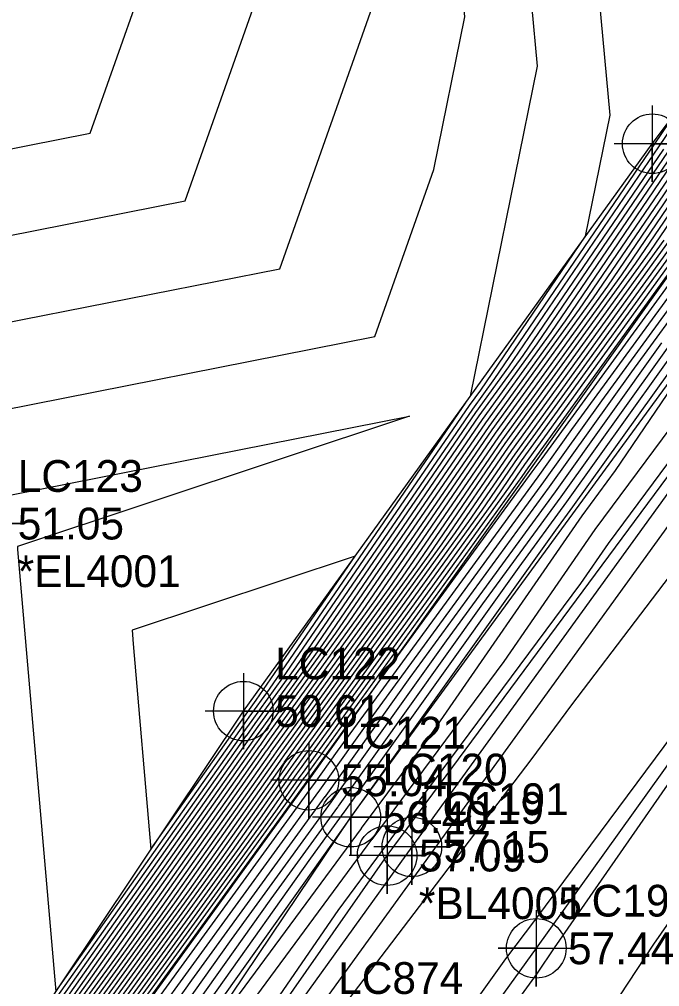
# Model space of a CAD drawing. Extents: x 2188792 to 2191981, y 386090 to 389710.
# Drawn here: x 2190040.5 to 2190090.9, y 387535.2 to 387611.4 of the extents above; entities that cross this region are included whole.
import ezdxf

# ---------------------------------------------------------------- set-up
doc = ezdxf.new("R2010")
doc.units = 0
for name, color, linetype in [('DTM Contours Major', 7, 'Continuous'), ('DTM Contours Minor', 7, 'Continuous'), ('Exist DTM Breakline', 7, 'Continuous'), ('Exist DTM Breakline Cogo Comment', 7, 'Continuous'), ('Exist DTM Breakline Cogo Elevation', 7, 'Continuous'), ('Exist DTM Breakline Cogo Number', 7, 'Continuous'), ('Exist DTM Breakline Cogo Point CELL', 7, 'Continuous'), ('Exist DTM Regular Point Underwater CELL', 7, 'Continuous'), ('Exist DTM Regular Point Underwater Cogo Comment', 7, 'Continuous'), ('Exist DTM Regular Point Underwater Cogo Elevation', 7, 'Continuous'), ('Exist DTM Regular Point Underwater Cogo Number', 7, 'Continuous'), ('Exist Roads EOP', 7, 'Continuous'), ('Exist Roads EOP Cogo Elevation', 7, 'Continuous'), ('Exist Roads EOP Cogo Number', 7, 'Continuous'), ('Exist Roads EOP Cogo Point CELL', 7, 'Continuous'), ('Exist Roads EOT', 7, 'Continuous'), ('Exist Roads EOT Cogo Elevation', 7, 'Continuous'), ('Exist Roads EOT Cogo Number', 7, 'Continuous'), ('Exist Roads EOT Cogo Point CELL', 7, 'Continuous')]:
    doc.layers.add(name, color=color, linetype=linetype)

msp = doc.modelspace()

# ---------------------------------------------------------------- linework, layer by layer
at = {"layer": 'DTM Contours Major'}
for points in [[(2190028.053, 387532.529), (2190026.213, 387539.316), (2190026.623, 387567.116), (2190036.437, 387572.281), (2190036.783, 387572.463), (2190037.624, 387573.49), (2190071.228, 387580.123), (2190040.365, 387569.873), (2190040.385, 387569.638), (2190043.386, 387534.826), (2190057.87, 387555.38), (2190057.878, 387555.392), (2190058.608, 387556.427), (2190060.211, 387558.646), (2190075.692, 387581.242), (2190075.723, 387581.285), (2190076.015, 387581.713), (2190081.298, 387607.701), (2190080.405, 387617.391)], [(2190041.85, 387529.933), (2190045.968, 387535.612), (2190059.191, 387554.377), (2190059.222, 387554.419), (2190059.771, 387555.199), (2190065.441, 387563.047), (2190076.972, 387579.879), (2190081.274, 387585.826), (2190091.608, 387600.993)], [(2190043.082, 387528.982), (2190051.636, 387540.776), (2190060.512, 387553.373), (2190060.566, 387553.447), (2190060.935, 387553.97), (2190070.671, 387567.449), (2190078.253, 387578.516), (2190086.825, 387590.366), (2190093.476, 387600.128)], [(2190045.546, 387527.079), (2190062.971, 387551.105), (2190063.155, 387551.367), (2190063.253, 387551.502), (2190063.261, 387551.513), (2190069.311, 387559.89), (2190080.892, 387575.741), (2190081.657, 387576.812), (2190097.263, 387598.2)], [(2190044.314, 387528.031), (2190057.303, 387545.941), (2190061.834, 387552.37), (2190061.909, 387552.475), (2190062.098, 387552.742), (2190075.901, 387571.851), (2190079.533, 387577.153), (2190092.376, 387594.907)], [(2190101.482, 387589.813), (2190086.86, 387570.121), (2190084.677, 387566.96), (2190069.08, 387545.942), (2190069.078, 387545.939), (2190065.584, 387541.202), (2190052.374, 387521.969)], [(2190048.167, 387524.986), (2190060.341, 387542.129), (2190065.593, 387549.358), (2190065.604, 387549.374), (2190065.633, 387549.414), (2190077.003, 387565.35), (2190083.158, 387573.776), (2190093.446, 387588.169)]]:
    msp.add_lwpolyline(points, dxfattribs=at)
at = {"layer": 'DTM Contours Minor'}
for points in [[(2190041.434, 387531.48), (2190058.134, 387555.179), (2190058.147, 387555.197), (2190058.841, 387556.182), (2190061.257, 387559.526), (2190075.948, 387580.969), (2190076.833, 387582.193), (2190085.083, 387594.302), (2190087.019, 387603.827), (2190085.629, 387618.912), (2190087.935, 387650.876), (2190087.053, 387661.979), (2190083.637, 387669.869), (2190092.461, 387664.589), (2190104.715, 387704.3), (2190094.611, 387735.217), (2190126.327, 387750.033), (2190141.347, 387755.069), (2190142.392, 387756.181), (2190147.502, 387770.178)], [(2190042.568, 387532.513), (2190058.398, 387554.979), (2190058.416, 387555.003), (2190059.074, 387555.936), (2190062.303, 387560.406), (2190076.204, 387580.697), (2190077.944, 387583.101), (2190090.487, 387601.512), (2190092.344, 387604.259), (2190090.853, 387620.433), (2190093.943, 387663.261), (2190094.289, 387663.295), (2190094.138, 387663.453), (2190094.078, 387663.515), (2190094.046, 387663.548), (2190094.035, 387663.572), (2190093.954, 387663.755), (2190107.097, 387706.348), (2190098.544, 387732.517), (2190125.391, 387745.059), (2190141.257, 387750.378), (2190143.628, 387752.535), (2190146.165, 387752.534), (2190150.45, 387767.809)], [(2189984.526, 387532.738), (2189985.313, 387544.525), (2189983.467, 387548.799), (2189986.676, 387548.086), (2189986.906, 387548.117), (2189997.205, 387555.605), (2189997.778, 387556.129), (2189998.069, 387556.592), (2190001.808, 387564.061), (2190025.826, 387576.7), (2190028.696, 387578.211), (2190035.675, 387586.738), (2190061.031, 387591.743), (2190069.081, 387614.559), (2190069.859, 387615.525), (2190068.063, 387633.741), (2190066.198, 387657.229), (2190065.615, 387658.574), (2190075.795, 387674.685), (2190075.782, 387675.298), (2190088.219, 387667.856), (2190097.569, 387698.156), (2190082.81, 387743.315), (2190129.137, 387764.957)], [(2190027.247, 387517.328), (2189992.67, 387537.316), (2189992.479, 387538.021), (2189991.936, 387551.2), (2189998.062, 387555.653), (2189998.198, 387555.778), (2189998.267, 387555.888), (2189999.156, 387557.664), (2190031.132, 387574.491), (2190032.739, 387575.337), (2190036.649, 387580.114), (2190068.493, 387586.4), (2190073.131, 387599.545), (2190075.577, 387611.576), (2190075.181, 387615.87), (2190075.838, 387624.97), (2190073.15, 387658.812), (2190070.209, 387665.603), (2190075.916, 387674.635), (2190075.909, 387674.98), (2190089.633, 387666.767), (2190099.951, 387700.204), (2190086.743, 387740.615), (2190128.2, 387759.982)], [(2190065.514, 387514.559), (2190081.303, 387536.264), (2190082.63, 387538.282), (2190097.61, 387559.851), (2190098.692, 387561.489), (2190115.183, 387585.188), (2190115.572, 387585.629), (2190129.097, 387601.222), (2190133.281, 387605.947), (2190145.736, 387620.245), (2190151.288, 387627.466), (2190156.609, 387634.62), (2190165.07, 387645.609), (2190174.107, 387657.741), (2190181.981, 387667.906), (2190187.788, 387675.299), (2190199.057, 387689.861), (2190205.414, 387697.968), (2190216.141, 387711.606), (2190219.575, 387716.076), (2190234.549, 387735.079)], [(2189947.255, 387575.706), (2189962.434, 387565.874), (2189963.546, 387564.645), (2189980.157, 387550.013), (2189986.384, 387548.629), (2189986.919, 387548.701), (2189996.347, 387555.556), (2189997.358, 387556.481), (2189997.871, 387557.295), (2190004.459, 387570.458), (2190020.52, 387578.91), (2190024.652, 387581.084), (2190034.7, 387593.362), (2190053.569, 387597.086), (2190059.559, 387614.065)], [(2189949.058, 387575.426), (2189962.83, 387566.507), (2189965.356, 387563.714), (2189980.438, 387550.429), (2189986.092, 387549.173), (2189986.932, 387549.285), (2189995.49, 387555.508), (2189996.939, 387556.832), (2189997.673, 387557.999), (2190007.111, 387576.856), (2190015.215, 387581.12), (2190020.608, 387583.958), (2190033.725, 387599.986), (2190046.106, 387602.43), (2190050.037, 387613.57)], [(2190043.701, 387533.546), (2190058.663, 387554.778), (2190058.685, 387554.808), (2190059.306, 387555.69), (2190063.349, 387561.287), (2190076.46, 387580.424), (2190079.054, 387584.009), (2190090.86, 387601.339), (2190097.123, 387610.601)], [(2190044.835, 387534.579), (2190058.927, 387554.577), (2190058.953, 387554.614), (2190059.539, 387555.444), (2190064.395, 387562.167), (2190076.716, 387580.151), (2190080.164, 387584.918), (2190091.234, 387601.166)], [(2190042.096, 387529.743), (2190047.102, 387536.645), (2190059.455, 387554.176), (2190059.491, 387554.225), (2190060.004, 387554.953), (2190066.487, 387563.928), (2190077.228, 387579.606), (2190082.385, 387586.734), (2190091.981, 387600.82)], [(2190042.343, 387529.553), (2190048.235, 387537.678), (2190059.72, 387553.975), (2190059.76, 387554.03), (2190060.237, 387554.707), (2190067.533, 387564.808), (2190077.484, 387579.334), (2190083.495, 387587.642), (2190092.355, 387600.647)], [(2190042.589, 387529.363), (2190049.369, 387538.711), (2190059.984, 387553.775), (2190060.028, 387553.836), (2190060.469, 387554.462), (2190068.579, 387565.688), (2190077.74, 387579.061), (2190084.605, 387588.55), (2190092.729, 387600.474)], [(2190042.836, 387529.172), (2190050.502, 387539.743), (2190060.248, 387553.574), (2190060.297, 387553.641), (2190060.702, 387554.216), (2190069.625, 387566.569), (2190077.997, 387578.788), (2190085.715, 387589.458), (2190093.102, 387600.301)], [(2190043.329, 387528.792), (2190052.769, 387541.809), (2190060.777, 387553.173), (2190060.835, 387553.252), (2190061.167, 387553.724), (2190071.717, 387568.329), (2190078.509, 387578.243), (2190087.936, 387591.275), (2190093.85, 387599.955)], [(2190043.575, 387528.601), (2190053.903, 387542.842), (2190061.041, 387552.972), (2190061.103, 387553.058), (2190061.4, 387553.479), (2190072.763, 387569.21), (2190078.765, 387577.97), (2190089.046, 387592.183), (2190094.223, 387599.782)], [(2190043.821, 387528.411), (2190055.036, 387543.875), (2190061.305, 387552.771), (2190061.372, 387552.863), (2190061.632, 387553.233), (2190073.809, 387570.09), (2190079.021, 387577.698), (2190090.156, 387593.091), (2190094.597, 387599.609)], [(2190045.3, 387527.269), (2190061.837, 387550.072), (2190062.89, 387551.567), (2190062.984, 387551.697), (2190063.028, 387551.759), (2190080.085, 387575.372), (2190080.557, 387576.062), (2190096.817, 387598.54)], [(2190045.054, 387527.46), (2190060.704, 387549.039), (2190062.626, 387551.768), (2190062.716, 387551.891), (2190062.796, 387552.004), (2190079.039, 387574.492), (2190080.301, 387576.335), (2190095.707, 387597.631)], [(2190047.848, 387529.313), (2190063.603, 387551), (2190063.605, 387551.003), (2190063.693, 387551.124), (2190065.565, 387553.748), (2190081.346, 387575.348), (2190084.015, 387579.083), (2190097.688, 387597.823)], [(2190050.971, 387532.517), (2190064.1, 387550.59), (2190064.104, 387550.596), (2190064.178, 387550.696), (2190068.424, 387556.649), (2190081.799, 387574.955), (2190086.373, 387581.355), (2190098.113, 387597.446)], [(2190044.807, 387527.65), (2190059.57, 387548.006), (2190062.362, 387551.969), (2190062.447, 387552.086), (2190062.563, 387552.25), (2190077.993, 387573.612), (2190080.045, 387576.607), (2190094.597, 387596.723)], [(2190047.085, 387525.851), (2190054.095, 387535.721), (2190064.598, 387550.179), (2190064.604, 387550.188), (2190064.663, 387550.269), (2190071.284, 387559.549), (2190082.252, 387574.562), (2190088.731, 387583.626), (2190098.538, 387597.069)], [(2190044.561, 387527.84), (2190058.437, 387546.974), (2190062.098, 387552.169), (2190062.178, 387552.28), (2190062.33, 387552.496), (2190076.947, 387572.731), (2190079.789, 387576.88), (2190093.487, 387595.815)], [(2190044.068, 387528.221), (2190056.17, 387544.908), (2190061.569, 387552.571), (2190061.641, 387552.669), (2190061.865, 387552.987), (2190074.855, 387570.971), (2190079.277, 387577.425), (2190091.266, 387593.999)], [(2190098.161, 387592.713), (2190084.065, 387572.99), (2190082.722, 387571.151), (2190066.635, 387548.603), (2190066.609, 387548.565), (2190066.604, 387548.558), (2190066.588, 387548.537), (2190066.588, 387548.537), (2190049.25, 387524.121)], [(2190098.32, 387591.907), (2190087.424, 387575.855), (2190084.778, 387572.291), (2190072.632, 387554.697), (2190067.429, 387547.686), (2190067.418, 387547.671), (2190051.466, 387526.048)], [(2190048.709, 387524.553), (2190063.465, 387545.333), (2190066.09, 387548.947), (2190066.104, 387548.966), (2190066.118, 387548.986), (2190079.862, 387568.251), (2190083.612, 387573.383), (2190095.804, 387590.441)], [(2190047.626, 387525.418), (2190057.218, 387538.925), (2190065.095, 387549.769), (2190065.104, 387549.781), (2190065.148, 387549.841), (2190074.143, 387562.45), (2190082.705, 387574.169), (2190091.088, 387585.898)], [(2190094.453, 387582.834), (2190085.819, 387571.206), (2190078.655, 387560.828), (2190068.255, 387546.814), (2190068.248, 387546.805), (2190057.272, 387531.926)], [(2190065.491, 387532.944), (2190080.791, 387553.075), (2190084.006, 387557.4), (2190094.856, 387571.695)], [(2190066.946, 387569.123), (2190049.393, 387563.293), (2190049.487, 387562.201), (2190050.88, 387546.037), (2190057.606, 387555.581), (2190057.61, 387555.586), (2190058.376, 387556.673), (2190059.165, 387557.765), (2190066.946, 387569.123)], [(2190096.333, 387560.967), (2190081.138, 387540.528), (2190078.772, 387537.414), (2190063.592, 387516.122)], [(2190096.147, 387546.786), (2190090.433, 387538.558), (2190081.858, 387525.513)]]:
    msp.add_lwpolyline(points, dxfattribs=at)
at = {"layer": 'Exist DTM Breakline'}
for points in [[(2189985.78, 387458.197), (2190024.035, 387505.879), (2190058.15, 387556.911), (2190090.329, 387601.585), (2190123.453, 387645.538), (2190155.634, 387692.318), (2190180.541, 387728.105)], [(2189992.243, 387453.105), (2190028.023, 387502.725), (2190063.31, 387551.461), (2190096.85, 387598.566), (2190127.537, 387642.384), (2190160.72, 387688.44), (2190186.991, 387724.396)], [(2189995.924, 387449.921), (2190033.109, 387498.748), (2190066.603, 387548.559), (2190100.696, 387595.155), (2190131.134, 387639.583), (2190163.791, 387685.951), (2190192.781, 387722.608)], [(2189998.889, 387447.645), (2190035.636, 387497.082), (2190069.466, 387545.534), (2190104.367, 387592.678), (2190135.108, 387636.538), (2190168.392, 387682.449), (2190194.386, 387718.656)]]:
    msp.add_lwpolyline(points, dxfattribs=at)
at = {"layer": 'Exist DTM Breakline Cogo Point CELL'}
for points in [[(2190090.329, 387604.585), (2190090.329, 387598.585), (2190090.329, 387601.585), (2190093.329, 387601.585), (2190087.329, 387601.585)], [(2190058.15, 387559.911), (2190058.15, 387553.911), (2190058.15, 387556.911), (2190061.15, 387556.911), (2190055.15, 387556.911)], [(2190063.31, 387554.461), (2190063.31, 387548.461), (2190063.31, 387551.461), (2190066.31, 387551.461), (2190060.31, 387551.461)], [(2190066.603, 387551.559), (2190066.603, 387545.559), (2190066.603, 387548.559), (2190069.603, 387548.559), (2190063.603, 387548.559)], [(2190069.466, 387548.534), (2190069.466, 387542.534), (2190069.466, 387545.534), (2190072.466, 387545.534), (2190066.466, 387545.534)]]:
    msp.add_lwpolyline(points, dxfattribs=at)
for centre in [(2190090.329, 387601.585), (2190058.15, 387556.911), (2190063.31, 387551.461), (2190066.603, 387548.559), (2190069.466, 387545.534)]:
    msp.add_circle(centre, 2.344, dxfattribs=at)
at = {"layer": 'Exist DTM Regular Point Underwater CELL'}
msp.add_lwpolyline([(2190037.891, 387574.675), (2190037.891, 387568.675), (2190037.891, 387571.675), (2190040.891, 387571.675), (2190034.891, 387571.675)], dxfattribs=at)
at = {"layer": 'Exist Roads EOP'}
msp.add_lwpolyline([(2190313.986, 387884.141), (2190285.547, 387843.636), (2190254.588, 387800.045), (2190225.155, 387759.32), (2190194.829, 387717.425), (2190164.291, 387675.101), (2190137.229, 387637.301), (2190105.098, 387592.774), (2190071.411, 387546.221), (2190039.296, 387501.568), (2190007.542, 387457.958), (2189976.844, 387415.407), (2189936.359, 387359.145), (2189907.138, 387318.716), (2189868.636, 387265.243), (2189836.428, 387220.463), (2189805.695, 387177.815), (2189775.592, 387135.957), (2189745.498, 387094.055), (2189715.496, 387052.249), (2189683.869, 387008.07), (2189653.218, 386965.867), (2189623.729, 386924.667)], dxfattribs=at)
at = {"layer": 'Exist Roads EOP Cogo Point CELL'}
msp.add_lwpolyline([(2190071.411, 387549.221), (2190071.411, 387543.221), (2190071.411, 387546.221), (2190074.411, 387546.221), (2190068.411, 387546.221)], dxfattribs=at)
msp.add_circle((2190071.411, 387546.221), 2.344, dxfattribs=at)
at = {"layer": 'Exist Roads EOT'}
for points in [[(2189910.407, 387320.236), (2189942.075, 387364.22), (2189970.438, 387403.768), (2190000.916, 387446.161), (2190032.053, 387489.248), (2190063.107, 387532.142), (2190093.978, 387574.79), (2190125.104, 387617.946), (2190155.102, 387659.638), (2190185.949, 387702.484), (2190216.886, 387745.11), (2190247.602, 387787.3), (2190276.876, 387828.015), (2190303.928, 387865.67), (2190323.039, 387892.195)], [(2190174.375, 387667.889), (2190147.471, 387630.495), (2190115.247, 387585.778), (2190081.202, 387538.232), (2190049.502, 387494.256), (2190017.538, 387450.182), (2189987.334, 387408.357), (2189946.666, 387352.019), (2189917.402, 387311.129), (2189878.955, 387257.772), (2189846.565, 387212.819), (2189815.837, 387170.306), (2189785.374, 387128.351), (2189755.717, 387086.921), (2189724.953, 387044.041), (2189693.727, 387000.805), (2189663.933, 386959.217), (2189633.425, 386917.196)]]:
    msp.add_lwpolyline(points, dxfattribs=at)
at = {"layer": 'Exist Roads EOT Cogo Point CELL'}
msp.add_lwpolyline([(2190081.202, 387541.232), (2190081.202, 387535.232), (2190081.202, 387538.232), (2190078.202, 387538.232), (2190084.202, 387538.232)], dxfattribs=at)
msp.add_circle((2190081.202, 387538.232), 2.344, dxfattribs=at)

# ---------------------------------------------------------------- texts
at = {"layer": 'Exist DTM Breakline Cogo Comment'}
msp.add_text('*BL4005', height=2.5, dxfattribs=at).set_placement((2190071.966, 387540.534))
at = {"layer": 'Exist DTM Breakline Cogo Elevation'}
for s, p in [('50.61', (2190060.65, 387555.661)), ('55.04', (2190065.81, 387550.211)), ('56.40', (2190069.103, 387547.309)), ('57.09', (2190071.966, 387544.284))]:
    msp.add_text(s, height=2.5, dxfattribs=at).set_placement(p)
at = {"layer": 'Exist DTM Breakline Cogo Number'}
for s, p in [('LC122', (2190060.65, 387559.411)), ('LC121', (2190065.81, 387553.961)), ('LC120', (2190069.103, 387551.059)), ('LC119', (2190071.966, 387548.034))]:
    msp.add_text(s, height=2.5, dxfattribs=at).set_placement(p)
at = {"layer": 'Exist DTM Regular Point Underwater Cogo Comment'}
msp.add_text('*EL4001', height=2.5, dxfattribs=at).set_placement((2190040.391, 387566.675))
at = {"layer": 'Exist DTM Regular Point Underwater Cogo Elevation'}
msp.add_text('51.05', height=2.5, dxfattribs=at).set_placement((2190040.391, 387570.425))
at = {"layer": 'Exist DTM Regular Point Underwater Cogo Number'}
msp.add_text('LC123', height=2.5, dxfattribs=at).set_placement((2190040.391, 387574.175))
at = {"layer": 'Exist Roads EOP Cogo Elevation'}
msp.add_text('57.15', height=2.5, dxfattribs=at).set_placement((2190073.911, 387544.971))
at = {"layer": 'Exist Roads EOP Cogo Number'}
msp.add_text('LC191', height=2.5, dxfattribs=at).set_placement((2190073.911, 387548.721))
at = {"layer": 'Exist Roads EOT Cogo Elevation'}
msp.add_text('57.44', height=2.5, dxfattribs=at).set_placement((2190083.702, 387536.982))
at = {"layer": 'Exist Roads EOT Cogo Number'}
for s, p in [('LC192', (2190083.702, 387540.732)), ('LC874', (2190065.607, 387534.642))]:
    msp.add_text(s, height=2.5, dxfattribs=at).set_placement(p)

doc.saveas('drawing.dxf')
